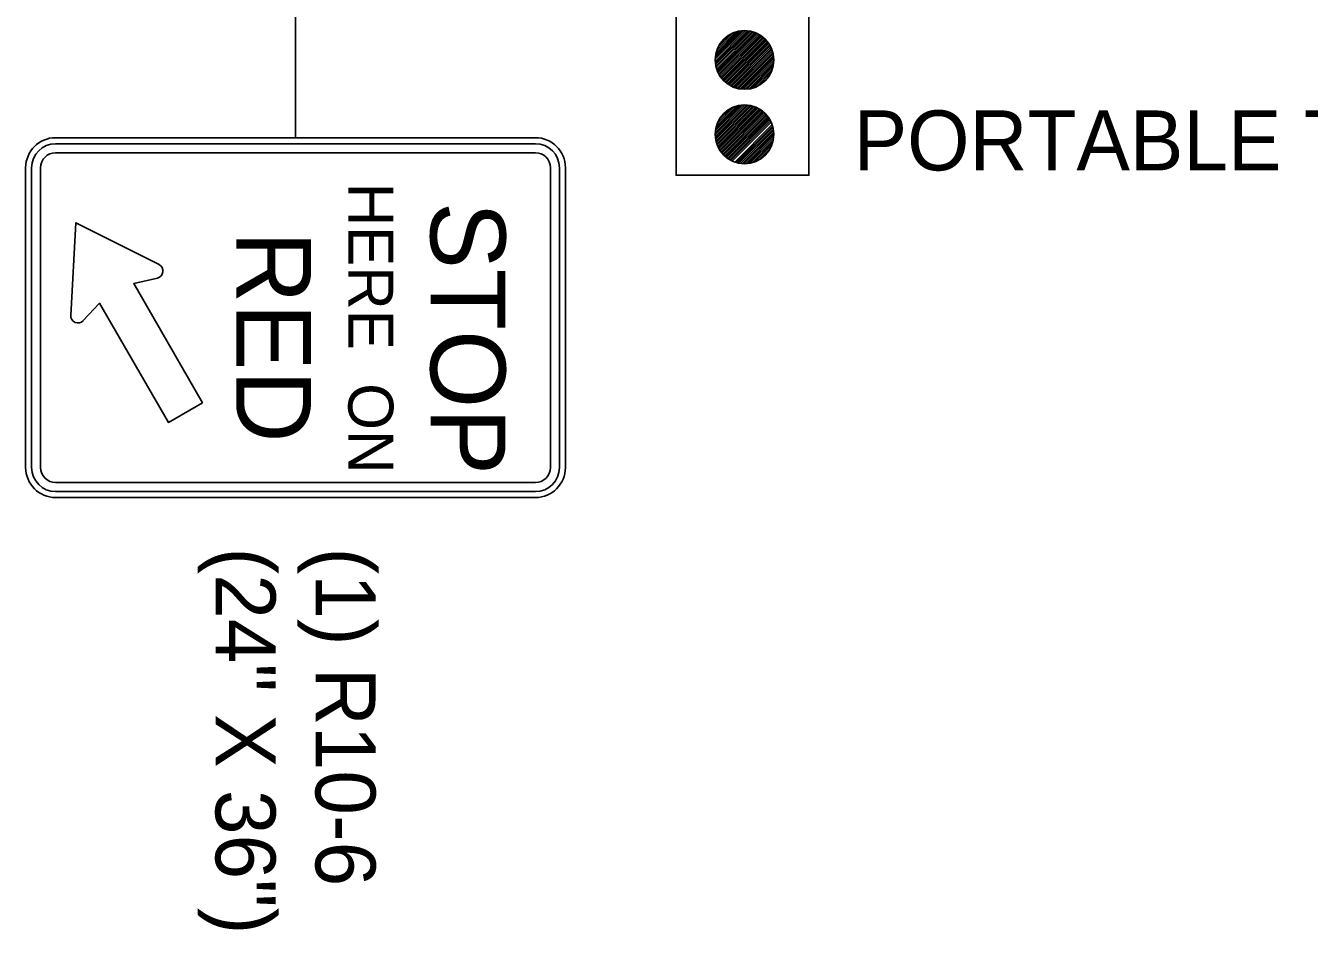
# Model space of a CAD drawing. Extents: x 1930579 to 1934718, y 596452 to 597844.
# Drawn here: x 1933047.5 to 1933176, y 597295 to 597385.4 of the extents above; entities that cross this region are included whole.
import ezdxf

# ---------------------------------------------------------------- set-up
doc = ezdxf.new("R2010")
doc.units = 0
for name, color, linetype in [('Default', 7, 'Continuous'), ('P_TC_Signs_Permanent', 7, 'Continuous'), ('R_Annotation', 7, 'Continuous')]:
    doc.layers.add(name, color=color, linetype=linetype)

msp = doc.modelspace()

# ---------------------------------------------------------------- linework, layer by layer
at = {"layer": 'Default'}
for p, q in [((1933116.5, 597382.06), (1933119.4, 597384.96)), ((1933116.51, 597381.88), (1933119.58, 597384.95)), ((1933116.51, 597382.25), (1933119.21, 597384.95)), ((1933116.52, 597381.71), (1933119.75, 597384.94)), ((1933116.54, 597382.45), (1933119.01, 597384.93)), ((1933116.54, 597381.55), (1933119.91, 597384.92)), ((1933116.57, 597381.4), (1933120.06, 597384.89)), ((1933116.58, 597382.68), (1933118.79, 597384.88)), ((1933116.6, 597381.25), (1933120.21, 597384.86)), ((1933116.65, 597381.11), (1933120.35, 597384.82)), ((1933116.65, 597382.93), (1933118.54, 597384.81)), ((1933116.69, 597380.98), (1933120.48, 597384.77)), ((1933116.74, 597380.85), (1933120.61, 597384.72)), ((1933116.76, 597383.22), (1933118.24, 597384.7)), ((1933116.8, 597380.73), (1933120.73, 597384.66)), ((1933116.86, 597380.61), (1933120.85, 597384.6)), ((1933116.93, 597380.49), (1933120.97, 597384.53)), ((1933116.98, 597383.62), (1933117.84, 597384.48)), ((1933117, 597380.38), (1933121.08, 597384.46)), ((1933117.07, 597380.28), (1933121.19, 597384.39)), ((1933117.15, 597380.17), (1933121.29, 597384.31)), ((1933117.24, 597380.08), (1933121.39, 597384.23)), ((1933117.32, 597379.98), (1933121.48, 597384.14)), ((1933117.41, 597379.89), (1933121.57, 597384.05)), ((1933117.51, 597379.8), (1933121.66, 597383.96)), ((1933117.61, 597379.72), (1933121.74, 597383.86)), ((1933117.71, 597379.64), (1933121.82, 597383.76)), ((1933117.81, 597379.57), (1933121.89, 597383.65)), ((1933117.92, 597379.5), (1933121.96, 597383.54)), ((1933118.04, 597379.43), (1933122.03, 597383.42)), ((1933118.16, 597379.37), (1933122.09, 597383.3)), ((1933118.28, 597379.31), (1933122.15, 597383.18)), ((1933118.41, 597379.26), (1933122.2, 597383.05)), ((1933118.55, 597379.22), (1933122.25, 597382.92)), ((1933118.69, 597379.17), (1933122.29, 597382.78)), ((1933118.83, 597379.14), (1933122.32, 597382.63)), ((1933118.98, 597379.11), (1933122.35, 597382.48)), ((1933119.14, 597379.09), (1933122.37, 597382.32)), ((1933119.31, 597379.08), (1933122.38, 597382.15)), ((1933119.49, 597379.07), (1933122.39, 597381.97)), ((1933119.68, 597379.08), (1933122.38, 597381.78)), ((1933119.88, 597379.11), (1933122.36, 597381.58)), ((1933120.11, 597379.15), (1933122.31, 597381.35)), ((1933120.36, 597379.22), (1933122.24, 597381.1)), ((1933120.65, 597379.33), (1933122.13, 597380.81)), ((1933121.05, 597379.55), (1933121.91, 597380.41)), ((1933116.5, 597374.54), (1933119.48, 597377.52)), ((1933116.51, 597374.72), (1933119.3, 597377.52)), ((1933116.51, 597374.37), (1933119.66, 597377.51)), ((1933116.52, 597374.92), (1933119.1, 597377.5)), ((1933116.53, 597374.2), (1933119.82, 597377.49)), ((1933116.55, 597374.05), (1933119.98, 597377.47)), ((1933116.56, 597375.14), (1933118.89, 597377.47)), ((1933116.58, 597373.9), (1933120.13, 597377.44)), ((1933116.61, 597375.37), (1933118.65, 597377.41)), ((1933116.62, 597373.75), (1933120.27, 597377.4)), ((1933116.67, 597373.62), (1933120.41, 597377.36)), ((1933116.7, 597375.64), (1933118.38, 597377.32)), ((1933116.72, 597373.48), (1933120.54, 597377.31)), ((1933116.77, 597373.36), (1933120.67, 597377.25)), ((1933116.83, 597373.24), (1933120.79, 597377.19)), ((1933116.86, 597375.98), (1933118.04, 597377.16)), ((1933116.89, 597373.12), (1933120.91, 597377.13)), ((1933116.96, 597373), (1933121.02, 597377.06)), ((1933117.03, 597372.9), (1933121.13, 597376.99)), ((1933117.11, 597372.79), (1933121.23, 597376.91)), ((1933117.19, 597372.69), (1933121.33, 597376.83)), ((1933117.27, 597372.59), (1933121.43, 597376.75)), ((1933117.36, 597372.5), (1933121.52, 597376.66)), ((1933117.45, 597372.41), (1933121.61, 597376.57)), ((1933117.55, 597372.33), (1933121.69, 597376.47)), ((1933117.65, 597372.25), (1933121.78, 597376.37)), ((1933117.75, 597372.17), (1933121.85, 597376.27)), ((1933117.86, 597372.1), (1933121.93, 597376.16)), ((1933117.97, 597372.03), (1933121.99, 597376.05)), ((1933118.09, 597371.97), (1933122.06, 597375.93)), ((1933118.21, 597371.91), (1933122.12, 597375.81)), ((1933118.47, 597371.8), (1933122.22, 597375.55)), ((1933118.61, 597371.76), (1933122.27, 597375.42)), ((1933118.75, 597371.72), (1933122.3, 597375.27)), ((1933118.9, 597371.69), (1933122.34, 597375.13)), ((1933119.05, 597371.66), (1933122.36, 597374.97)), ((1933119.22, 597371.64), (1933122.38, 597374.81)), ((1933119.39, 597371.64), (1933122.39, 597374.63)), ((1933119.57, 597371.64), (1933122.39, 597374.45)), ((1933119.77, 597371.65), (1933122.37, 597374.25)), ((1933119.98, 597371.68), (1933122.34, 597374.04)), ((1933120.21, 597371.74), (1933122.29, 597373.81)), ((1933120.48, 597371.82), (1933122.2, 597373.54)), ((1933120.81, 597371.97), (1933122.05, 597373.21)), ((1933121.38, 597372.36), (1933121.66, 597372.64))]:
    msp.add_line(p, q, dxfattribs=at)
msp.add_lwpolyline([(1933112.6, 597395.03), (1933125.89, 597395.03), (1933125.89, 597370.49), (1933112.6, 597370.49)], close=True, dxfattribs=at)
for centre in [(1933119.45, 597382.02), (1933119.45, 597374.58)]:
    msp.add_circle(centre, 2.94, dxfattribs=at)
at = {"layer": 'P_TC_Signs_Permanent'}
for p, q in [((1933050.54, 597374.24), (1933098.54, 597374.24)), ((1933050.54, 597373.64), (1933098.54, 597373.64)), ((1933050.54, 597372.74), (1933098.54, 597372.74)), ((1933047.54, 597341.24), (1933047.54, 597371.24)), ((1933048.14, 597341.24), (1933048.14, 597371.24)), ((1933049.04, 597341.24), (1933049.04, 597371.24)), ((1933100.04, 597371.24), (1933100.04, 597341.24)), ((1933100.94, 597371.24), (1933100.94, 597341.24)), ((1933101.54, 597371.24), (1933101.54, 597341.24)), ((1933098.54, 597339.74), (1933050.54, 597339.74)), ((1933098.54, 597338.84), (1933050.54, 597338.84)), ((1933098.54, 597338.24), (1933050.54, 597338.24))]:
    msp.add_line(p, q, dxfattribs=at)
for points in [[(1933060.88, 597361.54), (1933052.56, 597365.74), (1933052.05, 597356.47)], [(1933053.29, 597355.94), (1933054.94, 597357.68), (1933061.82, 597345.76), (1933065.23, 597347.73), (1933058.35, 597359.65), (1933060.72, 597360.2)]]:
    msp.add_lwpolyline(points, dxfattribs=at)
for centre, radius, start, end in [((1933050.54, 597371.24), 3, 90, 180), ((1933050.54, 597371.24), 2.4, 90, 180), ((1933098.54, 597371.24), 3, 360, 90), ((1933098.54, 597371.24), 2.4, 360, 90), ((1933050.54, 597371.24), 1.5, 90, 180), ((1933098.54, 597371.24), 1.5, 360, 90), ((1933060.55, 597360.9), 0.72, 283.0349, 63.2286), ((1933052.77, 597356.43), 0.72, 176.857, 316.6377), ((1933050.54, 597341.24), 3, 180, 270), ((1933050.54, 597341.24), 2.4, 180, 270), ((1933050.54, 597341.24), 1.5, 180, 270), ((1933098.54, 597341.24), 3, 270, 360), ((1933098.54, 597341.24), 2.4, 270, 360), ((1933098.54, 597341.24), 1.5, 270, 360)]:
    msp.add_arc(centre, radius, start, end, dxfattribs=at)
at = {"layer": 'R_Annotation'}
msp.add_line((1933074.54, 597390.67), (1933074.54, 597374.24), dxfattribs=at)

# ---------------------------------------------------------------- texts
at = {"layer": 'Default'}
msp.add_text('PORTABLE TRAFFIC SIGNAL SYSTEM', height=5.9996, rotation=360, dxfattribs=at).set_placement((1933130.37, 597370.97))
at = {"layer": 'P_TC_Signs_Permanent'}
for s, height, p in [('HERE  ON', 4.5, (1933079.82, 597369.74)), ('STOP', 7.5, (1933088.04, 597367.81)), ('RED', 7.5, (1933068.6, 597364.91))]:
    msp.add_text(s, height=height, rotation=270, dxfattribs=at).set_placement(p)
at = {"layer": 'R_Annotation'}
for s, height, p in [('(24" X 36")', 5.9996, (1933066.54, 597333.24)), ('(1) R10-6', 6, (1933076.54, 597333.24))]:
    msp.add_text(s, height=height, rotation=270, dxfattribs=at).set_placement(p)

doc.saveas('drawing.dxf')
